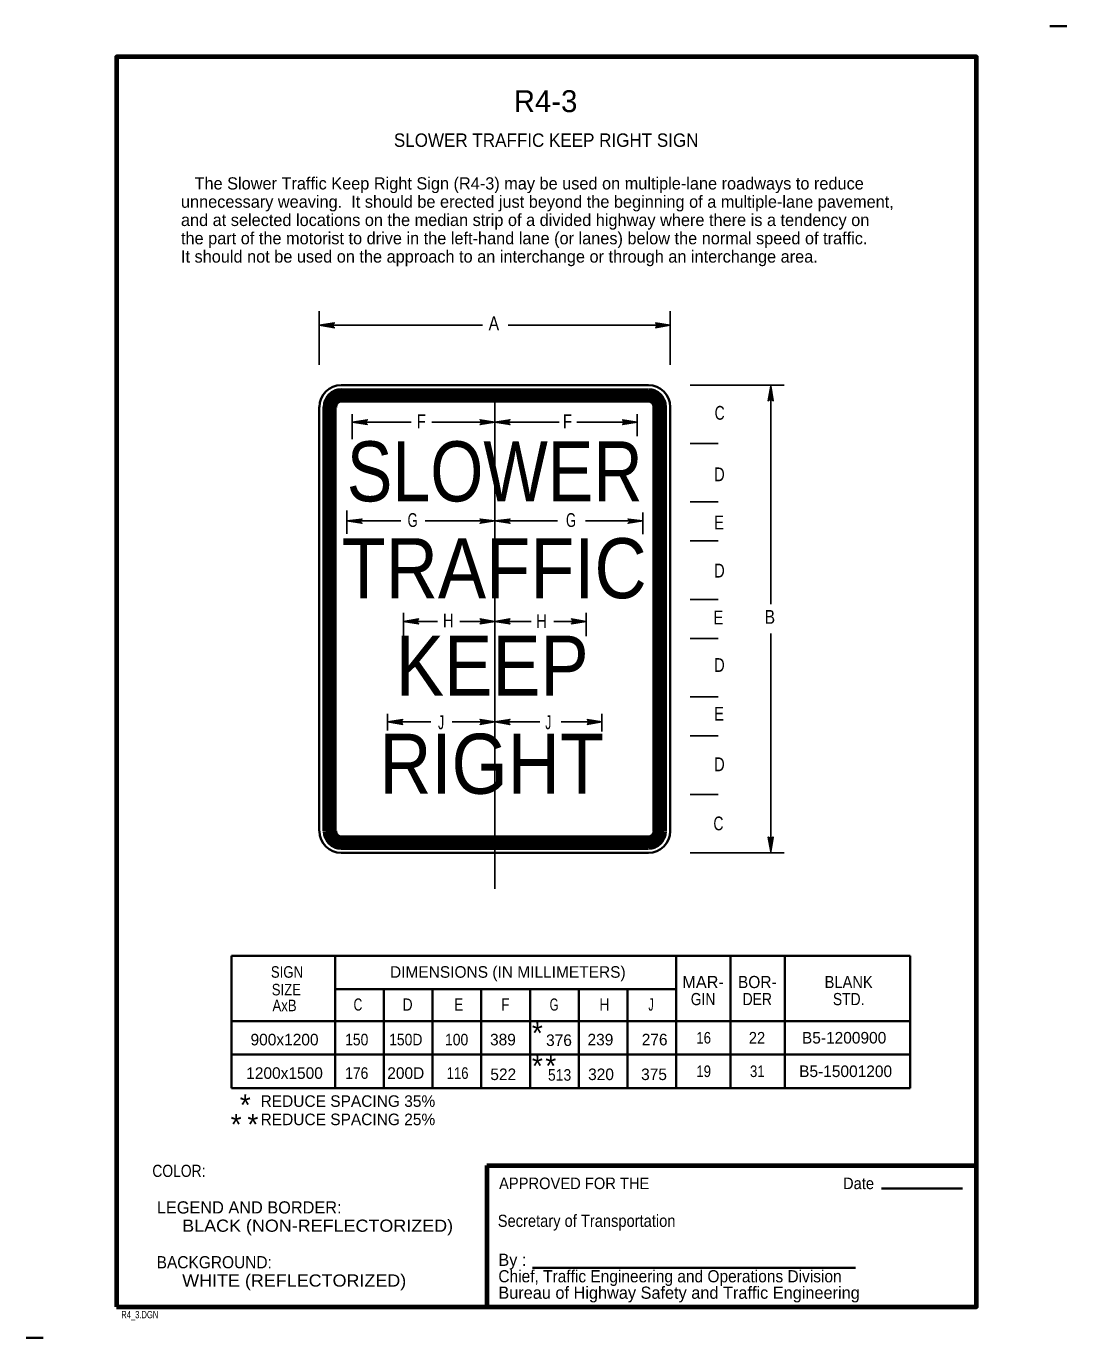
# Model space of a CAD drawing. Extents: x -0.018 to 0.195, y -0.006 to 0.263.
import ezdxf
from ezdxf.enums import TextEntityAlignment as Align

# ---------------------------------------------------------------- set-up
doc = ezdxf.new("R2010")
doc.units = 0
doc.header["$LTSCALE"] = 0.001
doc.linetypes.add('LONG_DASH_SHORT_DASH', pattern=[9.9, 6, -1.2, 1.5, -1.2])
doc.layers.add('1', color=7, linetype='Continuous', lineweight=25)
doc.layers.add('3', color=7, linetype='Continuous', lineweight=35)
doc.layers.add('2', color=7, linetype='Continuous')
doc.layers.add('6', color=7, linetype='Continuous')

msp = doc.modelspace()

# ---------------------------------------------------------------- linework, layer by layer
at = {"layer": '1', "lineweight": 35}
for p, q in [((0.195, 0.26275), (0.1915, 0.26275)), ((0.046125, 0.189125), (0.109125, 0.189125)), ((0.041625, 0.097625), (0.041625, 0.184625)), ((0.113625, 0.097625), (0.113625, 0.184625)), ((0.046125, 0.093125), (0.109125, 0.093125)), ((0.157, 0.02425), (0.173625, 0.02425)), ((0.085375, 0.008), (0.151625, 0.008)), ((-0.015, -0.006375), (-0.0185, -0.006375))]:
    msp.add_line(p, q, dxfattribs=at)
at = {"layer": '1'}
for p, q in [((0.041625, 0.19325), (0.041625, 0.20425)), ((0.113625, 0.19325), (0.113625, 0.20425)), ((0.041625, 0.201375), (0.075125, 0.201375)), ((0.113625, 0.201375), (0.080375, 0.201375)), ((0.11775, 0.189125), (0.137, 0.189125)), ((0.13425, 0.144125), (0.13425, 0.188875)), ((0.048375, 0.183125), (0.048375, 0.178)), ((0.106875, 0.183125), (0.106875, 0.178625)), ((0.0605, 0.1815), (0.048375, 0.1815)), ((0.077625, 0.1815), (0.06475, 0.1815)), ((0.077625, 0.1815), (0.090875, 0.1815)), ((0.0945, 0.1815), (0.106875, 0.1815)), ((0.11775, 0.177125), (0.1235, 0.177125)), ((0.11775, 0.165125), (0.1235, 0.165125)), ((0.04725, 0.158625), (0.04725, 0.163375)), ((0.108, 0.1585), (0.108, 0.163)), ((0.058375, 0.16125), (0.04725, 0.16125)), ((0.077625, 0.16125), (0.063375, 0.16125)), ((0.077625, 0.16125), (0.0905, 0.16125)), ((0.09625, 0.16125), (0.108, 0.16125)), ((0.11775, 0.157125), (0.1235, 0.157125)), ((0.11775, 0.145125), (0.1235, 0.145125)), ((0.058875, 0.13775), (0.058875, 0.142375)), ((0.065875, 0.140625), (0.058875, 0.140625)), ((0.077625, 0.140625), (0.0705, 0.140625)), ((0.077625, 0.140625), (0.085125, 0.140625)), ((0.08975, 0.140625), (0.096375, 0.140625)), ((0.096375, 0.137625), (0.096375, 0.142375)), ((0.13425, 0.138125), (0.13425, 0.093125)), ((0.11775, 0.137125), (0.1235, 0.137125)), ((0.11775, 0.125125), (0.1235, 0.125125)), ((0.055625, 0.11825), (0.055625, 0.121625)), ((0.099625, 0.118), (0.099625, 0.121625)), ((0.0645, 0.12), (0.055625, 0.12)), ((0.077625, 0.12), (0.068875, 0.12)), ((0.077625, 0.12), (0.086875, 0.12)), ((0.09125, 0.12), (0.099625, 0.12)), ((0.11775, 0.117125), (0.1235, 0.117125)), ((0.11775, 0.105125), (0.1235, 0.105125)), ((0.11775, 0.093125), (0.137, 0.093125))]:
    msp.add_line(p, q, dxfattribs=at)
at = {"layer": '1', "linetype": 'LONG_DASH_SHORT_DASH'}
msp.add_line((0.077625, 0.08575), (0.077625, 0.192), dxfattribs=at)
at = {"layer": '1', "lineweight": 106}
for p, q in [((0.046125, 0.187875), (0.109125, 0.187875)), ((0.046125, 0.186125), (0.109125, 0.186125)), ((0.042875, 0.097625), (0.042875, 0.184625)), ((0.04325, 0.097625), (0.04325, 0.184625)), ((0.04425, 0.097625), (0.04425, 0.184625)), ((0.044625, 0.097625), (0.044625, 0.184625)), ((0.110625, 0.097625), (0.110625, 0.184625)), ((0.112375, 0.097625), (0.112375, 0.184625)), ((0.046125, 0.096125), (0.109125, 0.096125)), ((0.046125, 0.095625), (0.109125, 0.095625)), ((0.046125, 0.09525), (0.109125, 0.09525)), ((0.046125, 0.09475), (0.109125, 0.09475)), ((0.046125, 0.094375), (0.109125, 0.094375))]:
    msp.add_line(p, q, dxfattribs=at)
at = {"layer": '1', "lineweight": 120}
for p, q in [((0.046125, 0.1875), (0.109125, 0.1875)), ((0.046125, 0.187), (0.109125, 0.187)), ((0.046125, 0.1865), (0.109125, 0.1865)), ((0.04375, 0.097625), (0.04375, 0.184625)), ((0.111125, 0.097625), (0.111125, 0.184625)), ((0.1115, 0.097625), (0.1115, 0.184625)), ((0.112, 0.097625), (0.112, 0.184625))]:
    msp.add_line(p, q, dxfattribs=at)
at = {"layer": '1', "lineweight": 70}
for q in [(0.1765, 0.029), (0.076, 0)]:
    msp.add_line((0.076, 0.029), q, dxfattribs=at)
msp.add_lwpolyline([(0, 0), (0.1765, 0), (0.1765, 0.2565), (0, 0.2565)], close=True, dxfattribs=at)
at = {"layer": '1'}
for points in [[(0.0445, 0.201), (0.0445, 0.20125), (0.041625, 0.201375), (0.0445, 0.201), (0.04475, 0.200875), (0.041625, 0.201375), (0.0445, 0.2015), (0.0445, 0.20175), (0.041625, 0.201375), (0.04475, 0.201875), (0.0445, 0.20175)], [(0.11075, 0.201), (0.110875, 0.20125), (0.113625, 0.201375), (0.11075, 0.201), (0.110625, 0.200875), (0.113625, 0.201375), (0.110875, 0.2015), (0.11075, 0.20175), (0.113625, 0.201375), (0.110625, 0.201875), (0.11075, 0.20175)], [(0.133875, 0.186), (0.134125, 0.186125), (0.13425, 0.188875), (0.133875, 0.186), (0.13375, 0.185875), (0.13425, 0.188875), (0.134375, 0.186125), (0.134625, 0.186), (0.13425, 0.188875), (0.13475, 0.185875), (0.134625, 0.186)], [(0.05125, 0.181875), (0.05125, 0.181625), (0.048375, 0.1815), (0.05125, 0.181875), (0.0515, 0.182), (0.048375, 0.1815), (0.05125, 0.181375), (0.05125, 0.181125), (0.048375, 0.1815), (0.0515, 0.181), (0.05125, 0.181125)], [(0.07475, 0.181875), (0.074875, 0.181625), (0.077625, 0.1815), (0.07475, 0.181875), (0.074625, 0.182), (0.077625, 0.1815), (0.074875, 0.181375), (0.07475, 0.181125), (0.077625, 0.1815), (0.074625, 0.181), (0.07475, 0.181125)], [(0.0805, 0.181875), (0.0805, 0.181625), (0.077625, 0.1815), (0.0805, 0.181875), (0.08075, 0.182), (0.077625, 0.1815), (0.0805, 0.181375), (0.0805, 0.181125), (0.077625, 0.1815), (0.08075, 0.181), (0.0805, 0.181125)], [(0.104, 0.181875), (0.104125, 0.181625), (0.106875, 0.1815), (0.104, 0.181875), (0.103875, 0.182), (0.106875, 0.1815), (0.104125, 0.181375), (0.104, 0.181125), (0.106875, 0.1815), (0.103875, 0.181), (0.104, 0.181125)], [(0.050125, 0.160875), (0.050125, 0.161), (0.04725, 0.16125), (0.050125, 0.160875), (0.050375, 0.16075), (0.04725, 0.16125), (0.050125, 0.161375), (0.050125, 0.1615), (0.04725, 0.16125), (0.050375, 0.161625), (0.050125, 0.1615)], [(0.07475, 0.1615), (0.074875, 0.161375), (0.077625, 0.16125), (0.07475, 0.1615), (0.074625, 0.161625), (0.077625, 0.16125), (0.074875, 0.161), (0.07475, 0.160875), (0.077625, 0.16125), (0.074625, 0.16075), (0.07475, 0.160875)], [(0.0805, 0.160875), (0.0805, 0.161), (0.077625, 0.16125), (0.0805, 0.160875), (0.08075, 0.16075), (0.077625, 0.16125), (0.0805, 0.161375), (0.0805, 0.1615), (0.077625, 0.16125), (0.08075, 0.161625), (0.0805, 0.1615)], [(0.105125, 0.1615), (0.10525, 0.161375), (0.108, 0.16125), (0.105125, 0.1615), (0.105, 0.161625), (0.108, 0.16125), (0.10525, 0.161), (0.105125, 0.160875), (0.108, 0.16125), (0.105, 0.16075), (0.105125, 0.160875)], [(0.06175, 0.14025), (0.06175, 0.1405), (0.058875, 0.140625), (0.06175, 0.14025), (0.062, 0.140125), (0.058875, 0.140625), (0.06175, 0.14075), (0.06175, 0.140875), (0.058875, 0.140625), (0.062, 0.141125), (0.06175, 0.140875)], [(0.07475, 0.141), (0.074875, 0.14075), (0.077625, 0.140625), (0.07475, 0.141), (0.074625, 0.141125), (0.077625, 0.140625), (0.074875, 0.1405), (0.07475, 0.14025), (0.077625, 0.140625), (0.074625, 0.140125), (0.07475, 0.14025)], [(0.0805, 0.14025), (0.0805, 0.1405), (0.077625, 0.140625), (0.0805, 0.14025), (0.08075, 0.140125), (0.077625, 0.140625), (0.0805, 0.14075), (0.0805, 0.140875), (0.077625, 0.140625), (0.08075, 0.141125), (0.0805, 0.140875)], [(0.0935, 0.141), (0.093625, 0.14075), (0.096375, 0.140625), (0.0935, 0.141), (0.093375, 0.141125), (0.096375, 0.140625), (0.093625, 0.1405), (0.0935, 0.14025), (0.096375, 0.140625), (0.093375, 0.140125), (0.0935, 0.14025)], [(0.058625, 0.119625), (0.0585, 0.119875), (0.055625, 0.12), (0.058625, 0.119625), (0.05875, 0.1195), (0.055625, 0.12), (0.058375, 0.120125), (0.058625, 0.120375), (0.055625, 0.12), (0.05875, 0.1205), (0.058625, 0.120375)], [(0.07475, 0.120375), (0.074875, 0.120125), (0.077625, 0.12), (0.07475, 0.120375), (0.074625, 0.1205), (0.077625, 0.12), (0.074875, 0.119875), (0.07475, 0.119625), (0.077625, 0.12), (0.074625, 0.1195), (0.07475, 0.119625)], [(0.0805, 0.119625), (0.0805, 0.119875), (0.077625, 0.12), (0.0805, 0.119625), (0.08075, 0.1195), (0.077625, 0.12), (0.0805, 0.120125), (0.0805, 0.120375), (0.077625, 0.12), (0.08075, 0.1205), (0.0805, 0.120375)], [(0.09675, 0.120375), (0.096875, 0.120125), (0.099625, 0.12), (0.09675, 0.120375), (0.096625, 0.1205), (0.099625, 0.12), (0.096875, 0.119875), (0.09675, 0.119625), (0.099625, 0.12), (0.096625, 0.1195), (0.09675, 0.119625)], [(0.133875, 0.09625), (0.134125, 0.096125), (0.13425, 0.093375), (0.133875, 0.09625), (0.13375, 0.096375), (0.13425, 0.093375), (0.134375, 0.096125), (0.134625, 0.09625), (0.13425, 0.093375), (0.13475, 0.096375), (0.134625, 0.09625)]]:
    msp.add_lwpolyline(points, dxfattribs=at)
at = {"layer": '1', "lineweight": 35}
for centre, start, end in [((0.046154, 0.18461), 90, 180), ((0.109154, 0.18461), 0, 90), ((0.046154, 0.09761), 180, 270), ((0.109154, 0.09761), 270, 0)]:
    msp.add_arc(centre, 0.0045, start, end, dxfattribs=at)
at = {"layer": '1', "lineweight": 106}
for centre, radius, start, end in [((0.046154, 0.18461), 0.00325, 90, 180), ((0.046154, 0.18461), 0.002813, 90, 180), ((0.046154, 0.18461), 0.002376, 90, 180), ((0.046154, 0.18461), 0.001939, 90, 180), ((0.046154, 0.18461), 0.0015, 90, 180), ((0.109154, 0.18461), 0.00325, 0, 90), ((0.109154, 0.18461), 0.002813, 0, 90), ((0.109154, 0.18461), 0.002376, 0, 90), ((0.109154, 0.18461), 0.001939, 0, 90), ((0.109154, 0.18461), 0.0015, 0, 90), ((0.046154, 0.09761), 0.00325, 180, 270), ((0.046154, 0.09761), 0.002813, 180, 270), ((0.046154, 0.09761), 0.002376, 180, 270), ((0.046154, 0.09761), 0.001939, 180, 270), ((0.046154, 0.09761), 0.0015, 180, 270), ((0.109154, 0.09761), 0.002813, 270, 0), ((0.109154, 0.09761), 0.002376, 270, 0), ((0.109154, 0.09761), 0.001939, 270, 0), ((0.109154, 0.09761), 0.0015, 270, 0), ((0.109154, 0.09761), 0.00325, 270, 0)]:
    msp.add_arc(centre, radius, start, end, dxfattribs=at)
at = {"layer": '3'}
for p, q in [((0.023625, 0.072), (0.162875, 0.072)), ((0.023625, 0.072), (0.023625, 0.044875)), ((0.044875, 0.072), (0.044875, 0.044875)), ((0.114875, 0.072), (0.114875, 0.044875)), ((0.126, 0.072), (0.126, 0.044875)), ((0.137125, 0.072), (0.137125, 0.044875)), ((0.162875, 0.072), (0.162875, 0.044875)), ((0.114875, 0.065125), (0.044875, 0.065125)), ((0.054875, 0.065125), (0.054875, 0.044875)), ((0.064875, 0.065125), (0.064875, 0.044875)), ((0.074875, 0.065125), (0.074875, 0.044875)), ((0.084875, 0.065125), (0.084875, 0.044875)), ((0.094875, 0.065125), (0.094875, 0.044875)), ((0.104875, 0.065125), (0.104875, 0.044875)), ((0.023625, 0.058625), (0.162875, 0.058625)), ((0.023625, 0.05175), (0.162875, 0.05175)), ((0.023625, 0.044875), (0.162875, 0.044875))]:
    msp.add_line(p, q, dxfattribs=at)

# ---------------------------------------------------------------- texts
at = {"layer": '1'}
msp.add_text('R4-3', height=0.0045, dxfattribs=at).set_placement((0.088063, 0.245125), align=Align.CENTER)
at = {"layer": '1', "width": 0.95}
for s, height, p in [('SLOWER TRAFFIC KEEP RIGHT SIGN', 0.00275, (0.088188, 0.238)), ('APPROVED FOR THE', 0.002375, (0.093938, 0.024125)), ('Date ', 0.002375, (0.152688, 0.024125))]:
    msp.add_text(s, height=height, dxfattribs=at).set_placement(p, align=Align.CENTER)
at = {"layer": '1'}
for s, height, width, p in [('A', 0.002837, 0.85, (0.076375, 0.200375)), ('F', 0.002837, 0.8, (0.061625, 0.18025)), ('F', 0.002837, 0.8, (0.091625, 0.18025)), ('C', 0.002837, 0.75, (0.12275, 0.182)), ('D', 0.002837, 0.8, (0.122625, 0.169375)), ('G', 0.002837, 0.7, (0.05975, 0.16)), ('G', 0.002837, 0.7, (0.09225, 0.16)), ('E', 0.002837, 0.8, (0.122625, 0.1595)), ('D', 0.002837, 0.8, (0.122625, 0.149625)), ('E', 0.002837, 0.8, (0.1225, 0.14)), ('B', 0.002837, 0.85, (0.133, 0.140125)), ('H', 0.002837, 0.8, (0.067, 0.139375)), ('H', 0.002837, 0.8, (0.086125, 0.13925)), ('D', 0.002837, 0.8, (0.122625, 0.13025)), ('J', 0.002837, 0.65, (0.066, 0.1185)), ('J', 0.002837, 0.65, (0.088, 0.1185)), ('E', 0.002837, 0.8, (0.122625, 0.12025)), ('D', 0.002837, 0.8, (0.122625, 0.109875)), ('C', 0.002837, 0.75, (0.1225, 0.09775)), ('COLOR:', 0.0025, 0.85, (0.007375, 0.026625)), ('Secretary of Transportation', 0.0025, 0.9, (0.07825, 0.016375)), ('      BLACK (NON-REFLECTORIZED)', 0.0025, 1.1, (0.007375, 0.015375)), (' BACKGROUND:', 0.0025, 0.95, (0.007375, 0.007875)), ('      WHITE (REFLECTORIZED)', 0.0025, 1.1, (0.007375, 0.004125)), ('Chief, Traffic Engineering and Operations Division', 0.0025, 0.95, (0.078375, 0.005)), ('R4_3.DGN', 0.0015, 0.75, (0.001, -0.002375))]:
    msp.add_text(s, height=height, dxfattribs=dict(at, width=width)).set_placement(p)
for s, p in [(' LEGEND AND BORDER:', (0.007375, 0.019125)), ('By :', (0.078375, 0.008375)), ('Bureau of Highway Safety and Traffic Engineering', (0.078375, 0.001625))]:
    msp.add_text(s, height=0.0025, dxfattribs=at).set_placement(p)
at = {"layer": '2'}
for s, p in [('   The Slower Traffic Keep Right Sign (R4-3) may be used on multiple-lane roadways to reduce', (0.01325, 0.22925)), ('unnecessary weaving.  It should be erected just beyond the beginning of a multiple-lane pavement,', (0.01325, 0.2255)), ('and at selected locations on the median strip of a divided highway where there is a tendency on', (0.01325, 0.22175)), ('the part of the motorist to drive in the left-hand lane (or lanes) below the normal speed of traffic.', (0.01325, 0.218)), ('It should not be used on the approach to an interchange or through an interchange area.', (0.01325, 0.21425))]:
    msp.add_text(s, height=0.0025, dxfattribs=at).set_placement(p)
at = {"layer": '3'}
for s, height, p in [('DIMENSIONS (IN MILLIMETERS)', 0.002375, (0.080312, 0.0675)), ('MAR-', 0.0025, (0.120375, 0.065375)), ('*', 0.00432, (0.086375, 0.054)), ('900x1200', 0.002375, (0.0345, 0.053625)), ('389', 0.002375, (0.079313, 0.053625)), ('376', 0.002375, (0.090813, 0.0535)), ('239', 0.002375, (0.099312, 0.053625)), ('276', 0.002375, (0.110438, 0.053625)), ('B5-1200900', 0.002375, (0.149313, 0.054)), ('*', 0.00432, (0.086375, 0.04725)), ('*', 0.00432, (0.089125, 0.04725)), ('1200x1500', 0.002375, (0.0345, 0.04675)), ('200D', 0.002375, (0.059375, 0.04675)), ('522', 0.002375, (0.079375, 0.0465)), ('320', 0.002375, (0.099437, 0.0465)), ('375', 0.002375, (0.110313, 0.0465)), ('B5-15001200', 0.002375, (0.149625, 0.047125)), ('*', 0.00432, (0.026437, 0.03925)), ('REDUCE SPACING 35%', 0.002375, (0.0475, 0.041)), ('*', 0.00432, (0.024563, 0.03525)), ('*', 0.00432, (0.028, 0.03525)), ('REDUCE SPACING 25%', 0.002375, (0.0475, 0.03725))]:
    msp.add_text(s, height=height, dxfattribs=at).set_placement(p, align=Align.CENTER)
for s, height, width, p in [('SIGN', 0.002375, 0.85, (0.035, 0.0675)), ('BOR-', 0.0025, 0.95, (0.1315, 0.065375)), ('BLANK', 0.0025, 0.9, (0.15025, 0.065375)), ('SIZE', 0.002375, 0.85, (0.034875, 0.063875)), ('AxB', 0.002375, 0.85, (0.0345, 0.060625)), ('C', 0.0025, 0.75, (0.049563, 0.06075)), ('D', 0.0025, 0.85, (0.05975, 0.06075)), ('E', 0.0025, 0.8, (0.07025, 0.06075)), ('F', 0.0025, 0.8, (0.079813, 0.06075)), ('G', 0.0025, 0.7, (0.089813, 0.06075)), ('H', 0.0025, 0.85, (0.100125, 0.06075)), ('J', 0.0025, 0.65, (0.109688, 0.06075)), ('GIN', 0.0025, 0.85, (0.120375, 0.061875)), ('DER', 0.0025, 0.85, (0.1315, 0.061875)), ('STD.', 0.0025, 0.85, (0.15025, 0.061875)), ('150', 0.002375, 0.9, (0.049313, 0.053625)), ('150D', 0.002375, 0.9, (0.059375, 0.053625)), ('100', 0.002375, 0.9, (0.069812, 0.053625)), ('16', 0.002375, 0.85, (0.1205, 0.054)), ('22', 0.002375, 0.95, (0.131438, 0.054)), ('176', 0.002375, 0.9, (0.049313, 0.04675)), ('116', 0.002375, 0.85, (0.07, 0.04675)), ('513', 0.002375, 0.9, (0.090938, 0.046375)), ('19', 0.002375, 0.85, (0.1205, 0.047125)), ('31', 0.002375, 0.85, (0.1315, 0.047125))]:
    msp.add_text(s, height=height, dxfattribs=dict(at, width=width)).set_placement(p, align=Align.CENTER)
at = {"layer": '6'}
for s, width, p in [('SLOWER', 0.85, (0.077625, 0.16525)), ('TRAFFIC', 0.9, (0.0775, 0.145375)), ('KEEP', 0.9, (0.077125, 0.125375)), ('RIGHT', 0.9, (0.077, 0.10525))]:
    msp.add_text(s, height=0.01232, dxfattribs=dict(at, width=width)).set_placement(p, align=Align.CENTER)

doc.saveas('drawing.dxf')
